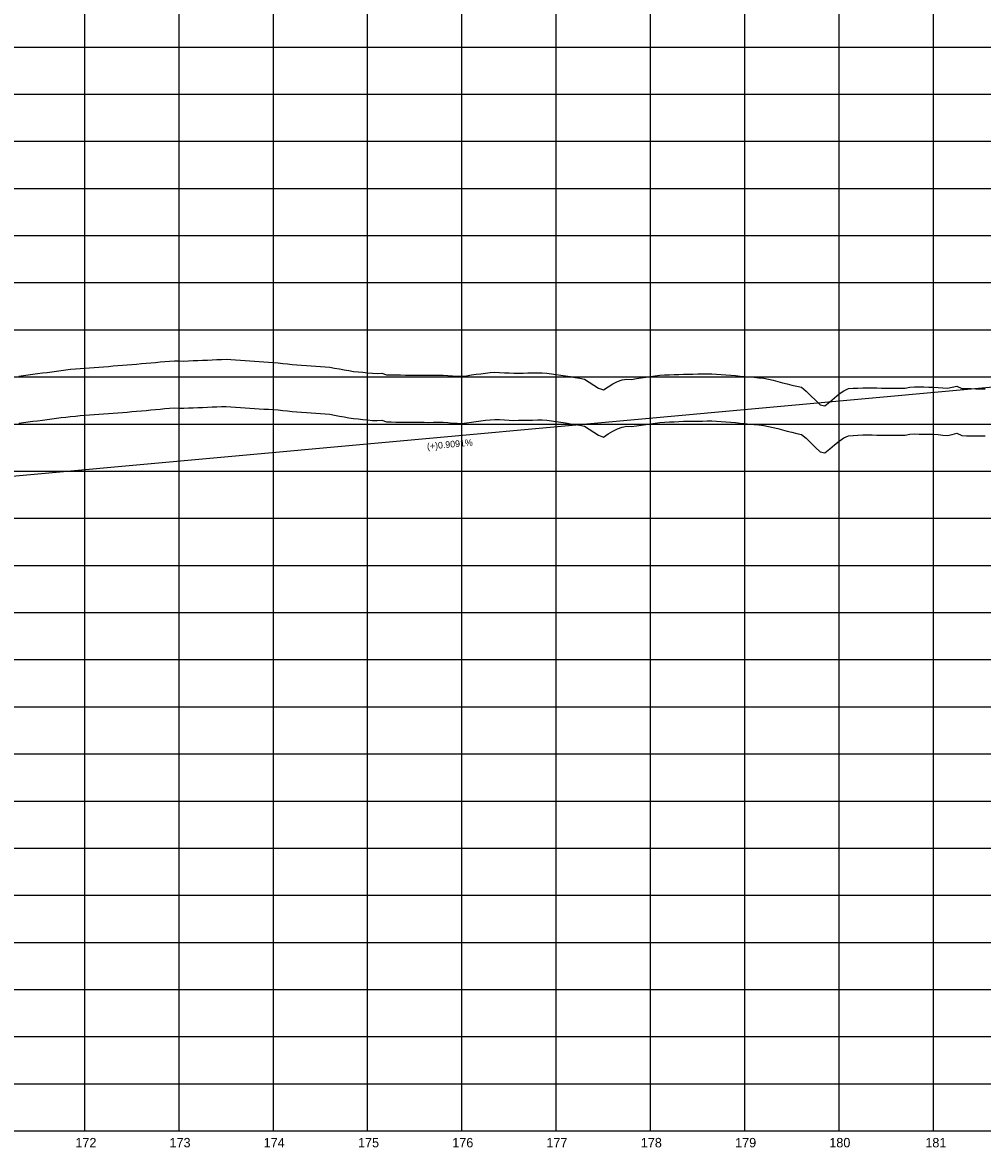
# Model space of a CAD drawing. Extents: x 2345490 to 2436403, y 465165 to 573888.
# Drawn here: x 2397455 to 2398474, y 564259 to 565453 of the extents above; entities that cross this region are included whole.
import ezdxf

# ---------------------------------------------------------------- set-up
doc = ezdxf.new("R2010")
doc.units = 0
for name, color, linetype in [('Old_Level_1', 7, 'Continuous'), ('Old_Level_2', 7, 'Continuous'), ('Old_Level_57', 7, 'Continuous'), ('Old_Level_62', 7, 'Continuous'), ('Old_Level_63', 7, 'Continuous')]:
    doc.layers.add(name, color=color, linetype=linetype)

msp = doc.modelspace()

# ---------------------------------------------------------------- linework, layer by layer
at = {"layer": 'Old_Level_1'}
for points in [[(2397451.5425, 565027.46875), (2397456.5425, 565028.1175), (2397461.5425, 565028.7665), (2397466.5425, 565029.41625), (2397471.5425, 565030.06625), (2397476.5425, 565030.7165), (2397481.5425, 565031.36725), (2397486.5425, 565032.0185), (2397491.5425, 565032.66975), (2397496.5425, 565033.3215), (2397501.5425, 565033.9735), (2397506.5425, 565034.6435), (2397511.5425, 565035.028), (2397516.5425, 565035.4135), (2397521.5425, 565035.7995), (2397526.5425, 565036.18575), (2397531.5425, 565036.572), (2397536.5425, 565036.9585), (2397541.5425, 565037.34475), (2397546.5425, 565037.73125), (2397551.5425, 565038.11775), (2397556.5425, 565038.504), (2397561.5425, 565038.87125), (2397566.5425, 565039.2175), (2397571.5425, 565039.67525), (2397576.5425, 565040.13325), (2397581.5425, 565040.59125), (2397586.5425, 565041.04925), (2397591.5425, 565041.507), (2397596.5425, 565041.965), (2397601.5425, 565042.423), (2397606.5425, 565042.881), (2397611.5425, 565043.33875), (2397616.5425, 565043.692), (2397621.5425, 565043.45175), (2397626.5425, 565043.3995), (2397631.5425, 565043.61025), (2397636.5425, 565043.82075), (2397641.5425, 565044.0315), (2397646.5425, 565044.24225), (2397651.5425, 565044.453), (2397656.5425, 565044.66375), (2397661.5425, 565044.87425), (2397666.5425, 565045.085), (2397671.5425, 565045.23025), (2397676.5425, 565044.883), (2397681.5425, 565044.53575), (2397686.5425, 565044.1885), (2397691.5425, 565043.8415), (2397696.5425, 565043.49425), (2397701.5425, 565043.147), (2397706.5425, 565042.79975), (2397711.5425, 565042.45825), (2397716.5425, 565042.1485), (2397721.5425, 565041.83875), (2397726.5425, 565041.50575), (2397731.5425, 565040.934), (2397736.5425, 565040.362), (2397741.5425, 565039.79025), (2397746.5425, 565039.33375), (2397751.5425, 565038.98775), (2397756.5425, 565038.64175), (2397761.5425, 565038.29575), (2397766.5425, 565037.94975), (2397771.5425, 565037.60375), (2397776.5425, 565037.25775), (2397781.5425, 565036.88175), (2397786.5425, 565035.95075), (2397791.5425, 565035.01975), (2397796.5425, 565034.08875), (2397801.5425, 565033.15775), (2397806.5425, 565032.35325), (2397811.5425, 565031.87325), (2397816.5425, 565031.3935), (2397821.5425, 565030.91375), (2397826.5425, 565030.434), (2397831.5425, 565030.1065), (2397836.5425, 565030.6725), (2397841.5425, 565028.777), (2397846.5425, 565028.70625), (2397851.5425, 565028.63575), (2397856.5425, 565028.565), (2397861.5425, 565028.51), (2397866.5425, 565028.47725), (2397871.5425, 565028.4445)], [(2397871.5425, 565028.4445), (2397876.5425, 565028.4115), (2397881.5425, 565028.37875), (2397886.5425, 565028.302), (2397891.5425, 565028.38125), (2397896.5425, 565028.538), (2397901.5425, 565028.5315), (2397906.5425, 565028.07125), (2397911.5425, 565027.611), (2397916.5425, 565027.3155), (2397921.5425, 565027.202), (2397926.5425, 565027.81325), (2397931.5425, 565028.598), (2397936.5425, 565029.364), (2397941.5425, 565029.94125), (2397946.5425, 565030.5185), (2397951.5425, 565031.09575), (2397956.5425, 565031.50725), (2397961.5425, 565031.24075), (2397966.5425, 565030.974), (2397971.5425, 565030.7075), (2397976.5425, 565030.44075), (2397981.5425, 565030.5155), (2397986.5425, 565030.64775), (2397991.5425, 565030.72575), (2397996.5425, 565030.80025), (2398001.5425, 565030.87475), (2398006.5425, 565030.88675), (2398011.5425, 565030.494), (2398016.5425, 565029.842), (2398021.5425, 565029.254), (2398026.5425, 565028.4445), (2398031.5425, 565027.635), (2398036.5425, 565026.82275), (2398041.5425, 565025.98475), (2398046.5425, 565025.176), (2398051.5425, 565024.1925), (2398056.5425, 565021.035), (2398061.5425, 565017.8775), (2398066.5425, 565014.72), (2398071.5425, 565012.761), (2398076.5425, 565016.1675), (2398081.5425, 565019.10675), (2398086.5425, 565021.56925), (2398091.5425, 565023.3685), (2398096.5425, 565024.22075), (2398101.5425, 565023.91375), (2398106.5425, 565024.713), (2398111.5425, 565025.427), (2398116.5425, 565026.14125), (2398121.5425, 565026.8555), (2398126.5425, 565027.56975), (2398131.5425, 565028.284), (2398136.5425, 565028.60275), (2398141.5425, 565028.78475), (2398146.5425, 565028.99425), (2398151.5425, 565029.20375), (2398156.5425, 565029.41325), (2398161.5425, 565029.48425), (2398166.5425, 565029.558), (2398171.5425, 565029.6315), (2398176.5425, 565029.705), (2398181.5425, 565029.7785), (2398186.5425, 565029.85225), (2398191.5425, 565029.5405), (2398196.5425, 565029.18525), (2398201.5425, 565028.83), (2398206.5425, 565028.47475), (2398211.5425, 565027.996), (2398216.5425, 565027.49325), (2398221.5425, 565027.016), (2398226.5425, 565026.554), (2398231.5425, 565026.08325), (2398236.5425, 565025.6125), (2398241.5425, 565025.05075), (2398246.5425, 565024.036), (2398251.5425, 565022.9735), (2398256.5425, 565021.66825), (2398261.5425, 565020.36275), (2398266.5425, 565019.1175), (2398271.5425, 565017.9365), (2398276.5425, 565016.6495), (2398281.5425, 565015.506), (2398286.5425, 565011.4535), (2398291.5425, 565006.60675), (2398296.5425, 565001.75975), (2398301.5425, 564996.91275), (2398306.5425, 564995.989), (2398311.5425, 565000.164), (2398316.5425, 565004.33925), (2398321.5425, 565008.5145), (2398326.5425, 565011.773), (2398331.5425, 565014.157), (2398336.5425, 565014.42525), (2398341.5425, 565014.6935), (2398346.5425, 565014.9615), (2398351.5425, 565015.107), (2398356.5425, 565014.97475), (2398361.5425, 565014.84275), (2398366.5425, 565014.7105), (2398371.5425, 565014.63575)], [(2398371.5425, 565014.63575), (2398376.5425, 565014.647), (2398381.5425, 565014.65825), (2398386.5425, 565014.6695), (2398391.5425, 565014.73525), (2398396.5425, 565015.76575), (2398401.5425, 565015.97825), (2398406.5425, 565015.9255), (2398411.5425, 565015.87275), (2398416.5425, 565015.82), (2398421.5425, 565015.74225), (2398426.5425, 565015.30925), (2398431.5425, 565014.87625), (2398436.5425, 565014.4875), (2398441.5425, 565015.56425), (2398446.5425, 565016.79025), (2398451.5425, 565014.18875), (2398456.5425, 565014.1245), (2398461.5425, 565014.06), (2398466.5425, 565013.9955), (2398471.5425, 565013.931), (2398476.5425, 565013.86675)]]:
    msp.add_lwpolyline(points, dxfattribs=at)
at = {"layer": 'Old_Level_2'}
msp.add_line((2396821.5425, 564914.71575), (2398621.5425, 565078.352), dxfattribs=at)
at = {"layer": 'Old_Level_57'}
for p, q in [((2397521.54225, 564276.534), (2397521.54225, 566615.2835)), ((2397621.54225, 564276.534), (2397621.54225, 566615.2835)), ((2397721.54225, 564276.534), (2397721.54225, 566615.2835)), ((2397821.54225, 564276.534), (2397821.54225, 566615.2835)), ((2397921.54225, 564276.534), (2397921.54225, 566615.2835)), ((2398021.54225, 564276.534), (2398021.54225, 566615.2835)), ((2398021.54225, 564276.534), (2398021.54225, 566615.2835)), ((2398121.54225, 564276.534), (2398121.54225, 566615.2835)), ((2398121.54225, 564276.534), (2398121.54225, 566615.2835)), ((2398221.54225, 564276.534), (2398221.54225, 566615.2835)), ((2398221.54225, 564276.534), (2398221.54225, 566615.2835)), ((2398321.5425, 564276.534), (2398321.5425, 566615.2835)), ((2398321.5425, 564276.534), (2398321.5425, 566615.2835)), ((2398421.54225, 564276.534), (2398421.54225, 566615.2835)), ((2381271.5425, 565426.534), (2410861.12275, 565426.534)), ((2381271.5425, 565376.534), (2410861.12275, 565376.534)), ((2381271.5425, 565326.534), (2410861.12275, 565326.534)), ((2381271.5425, 565276.534), (2410861.12275, 565276.534)), ((2381271.5425, 565226.534), (2410861.12275, 565226.534)), ((2381271.5425, 565176.534), (2410861.12275, 565176.534)), ((2381271.5425, 565126.534), (2410861.12275, 565126.534)), ((2381271.5425, 565076.534), (2410861.12275, 565076.534)), ((2381271.5425, 565026.534), (2410861.12275, 565026.534)), ((2381271.5425, 564976.534), (2410861.12275, 564976.534)), ((2381271.5425, 564926.534), (2410861.12275, 564926.534)), ((2381271.5425, 564876.534), (2410861.12275, 564876.534)), ((2381271.5425, 564826.534), (2410861.12275, 564826.534)), ((2381271.54275, 564776.534), (2410861.123, 564776.534)), ((2381271.5425, 564726.534), (2410861.12275, 564726.534)), ((2381271.54275, 564676.534), (2410861.123, 564676.534)), ((2381271.5425, 564626.534), (2410861.12275, 564626.534)), ((2381271.54275, 564576.534), (2410861.123, 564576.534)), ((2381271.5425, 564526.534), (2410861.12275, 564526.534)), ((2381271.54275, 564476.534), (2410861.123, 564476.534)), ((2381271.5425, 564426.534), (2410861.12275, 564426.534)), ((2381271.54275, 564376.534), (2410861.123, 564376.534)), ((2381271.5425, 564326.534), (2410861.12275, 564326.534)), ((2381271.54275, 564276.534), (2410861.123, 564276.534))]:
    msp.add_line(p, q, dxfattribs=at)
at = {"layer": 'Old_Level_63'}
msp.add_line((2381321.5425, 564276.534), (2406689.937, 564276.534), dxfattribs=at)
for points in [[(2397451.5425, 565077.4685), (2397456.5425, 565078.11725), (2397461.5425, 565078.76625), (2397466.5425, 565079.416), (2397471.5425, 565080.066), (2397476.5425, 565080.71625), (2397481.5425, 565081.367), (2397486.5425, 565082.01825), (2397491.5425, 565082.6695), (2397496.5425, 565083.32125), (2397501.5425, 565083.97325), (2397506.5425, 565084.64325), (2397511.5425, 565085.02775), (2397516.5425, 565085.41325), (2397521.5425, 565085.79925), (2397526.5425, 565086.1855), (2397531.5425, 565086.57175), (2397536.5425, 565086.95825), (2397541.5425, 565087.3445), (2397546.5425, 565087.731), (2397551.5425, 565088.1175), (2397556.5425, 565088.50375), (2397561.5425, 565088.871), (2397566.5425, 565089.21725), (2397571.5425, 565089.675), (2397576.5425, 565090.133), (2397581.5425, 565090.591), (2397586.5425, 565091.049), (2397591.5425, 565091.50675), (2397596.5425, 565091.96475), (2397601.5425, 565092.42275), (2397606.5425, 565092.88075), (2397611.5425, 565093.3385), (2397616.5425, 565093.69175), (2397621.5425, 565093.4515), (2397626.5425, 565093.39925), (2397631.5425, 565093.61), (2397636.5425, 565093.8205), (2397641.5425, 565094.03125), (2397646.5425, 565094.242), (2397651.5425, 565094.45275), (2397656.5425, 565094.6635), (2397661.5425, 565094.874), (2397666.5425, 565095.08475), (2397671.5425, 565095.23), (2397676.5425, 565094.88275), (2397681.5425, 565094.5355), (2397686.5425, 565094.18825), (2397691.5425, 565093.84125), (2397696.5425, 565093.494), (2397701.5425, 565093.14675), (2397706.5425, 565092.7995), (2397711.5425, 565092.458), (2397716.5425, 565092.14825), (2397721.5425, 565091.8385), (2397726.5425, 565091.5055), (2397731.5425, 565090.93375), (2397736.5425, 565090.36175), (2397741.5425, 565089.79), (2397746.5425, 565089.3335), (2397751.5425, 565088.9875), (2397756.5425, 565088.6415), (2397761.5425, 565088.2955), (2397766.5425, 565087.9495), (2397771.5425, 565087.6035), (2397776.5425, 565087.2575), (2397781.5425, 565086.8815), (2397786.5425, 565085.9505), (2397791.5425, 565085.0195), (2397796.5425, 565084.0885), (2397801.5425, 565083.1575), (2397806.5425, 565082.353), (2397811.5425, 565081.873), (2397816.5425, 565081.39325), (2397821.5425, 565080.9135), (2397826.5425, 565080.43375), (2397831.5425, 565080.10625), (2397836.5425, 565080.67225), (2397841.5425, 565078.77675), (2397846.5425, 565078.706), (2397851.5425, 565078.6355), (2397856.5425, 565078.56475), (2397861.5425, 565078.50975), (2397866.5425, 565078.477), (2397871.5425, 565078.44425)], [(2397871.5425, 565078.44425), (2397876.5425, 565078.41125), (2397881.5425, 565078.3785), (2397886.5425, 565078.30175), (2397891.5425, 565078.381), (2397896.5425, 565078.53775), (2397901.5425, 565078.53125), (2397906.5425, 565078.071), (2397911.5425, 565077.61075), (2397916.5425, 565077.31525), (2397921.5425, 565077.20175), (2397926.5425, 565077.813), (2397931.5425, 565078.59775), (2397936.5425, 565079.36375), (2397941.5425, 565079.941), (2397946.5425, 565080.51825), (2397951.5425, 565081.0955), (2397956.5425, 565081.507), (2397961.5425, 565081.2405), (2397966.5425, 565080.97375), (2397971.5425, 565080.70725), (2397976.5425, 565080.4405), (2397981.5425, 565080.51525), (2397986.5425, 565080.6475), (2397991.5425, 565080.7255), (2397996.5425, 565080.8), (2398001.5425, 565080.8745), (2398006.5425, 565080.8865), (2398011.5425, 565080.49375), (2398016.5425, 565079.84175), (2398021.5425, 565079.25375), (2398026.5425, 565078.44425), (2398031.5425, 565077.63475), (2398036.5425, 565076.8225), (2398041.5425, 565075.9845), (2398046.5425, 565075.17575), (2398051.5425, 565074.19225), (2398056.5425, 565071.03475), (2398061.5425, 565067.87725), (2398066.5425, 565064.71975), (2398071.5425, 565062.76075), (2398076.5425, 565066.16725), (2398081.5425, 565069.1065), (2398086.5425, 565071.569), (2398091.5425, 565073.36825), (2398096.5425, 565074.2205), (2398101.5425, 565073.9135), (2398106.5425, 565074.71275), (2398111.5425, 565075.42675), (2398116.5425, 565076.141), (2398121.5425, 565076.85525), (2398126.5425, 565077.5695), (2398131.5425, 565078.28375), (2398136.5425, 565078.6025), (2398141.5425, 565078.7845), (2398146.5425, 565078.994), (2398151.5425, 565079.2035), (2398156.5425, 565079.413), (2398161.5425, 565079.484), (2398166.5425, 565079.55775), (2398171.5425, 565079.63125), (2398176.5425, 565079.70475), (2398181.5425, 565079.77825), (2398186.5425, 565079.852), (2398191.5425, 565079.54025), (2398196.5425, 565079.185), (2398201.5425, 565078.82975), (2398206.5425, 565078.4745), (2398211.5425, 565077.99575), (2398216.5425, 565077.493), (2398221.5425, 565077.01575), (2398226.5425, 565076.55375), (2398231.5425, 565076.083), (2398236.5425, 565075.61225), (2398241.5425, 565075.0505), (2398246.5425, 565074.03575), (2398251.5425, 565072.97325), (2398256.5425, 565071.668), (2398261.5425, 565070.3625), (2398266.5425, 565069.11725), (2398271.5425, 565067.93625), (2398276.5425, 565066.64925), (2398281.5425, 565065.50575), (2398286.5425, 565061.45325), (2398291.5425, 565056.6065), (2398296.5425, 565051.7595), (2398301.5425, 565046.9125), (2398306.5425, 565045.98875), (2398311.5425, 565050.16375), (2398316.5425, 565054.339), (2398321.5425, 565058.51425), (2398326.5425, 565061.77275), (2398331.5425, 565064.15675), (2398336.5425, 565064.425), (2398341.5425, 565064.69325), (2398346.5425, 565064.96125), (2398351.5425, 565065.10675), (2398356.5425, 565064.9745), (2398361.5425, 565064.8425), (2398366.5425, 565064.71025), (2398371.5425, 565064.6355)], [(2398371.5425, 565064.6355), (2398376.5425, 565064.64675), (2398381.5425, 565064.658), (2398386.5425, 565064.66925), (2398391.5425, 565064.735), (2398396.5425, 565065.7655), (2398401.5425, 565065.978), (2398406.5425, 565065.92525), (2398411.5425, 565065.8725), (2398416.5425, 565065.81975), (2398421.5425, 565065.742), (2398426.5425, 565065.309), (2398431.5425, 565064.876), (2398436.5425, 565064.48725), (2398441.5425, 565065.564), (2398446.5425, 565066.79), (2398451.5425, 565064.1885), (2398456.5425, 565064.12425), (2398461.5425, 565064.05975), (2398466.5425, 565063.99525), (2398471.5425, 565063.93075), (2398476.5425, 565063.8665)]]:
    msp.add_lwpolyline(points, dxfattribs=at)

# ---------------------------------------------------------------- texts
at = {"layer": 'Old_Level_2'}
msp.add_text('(+)0.9091%', height=7.000001, rotation=5.19442778, dxfattribs=at).set_placement((2397884.76075, 564999.298))
at = {"layer": 'Old_Level_62'}
for s, p in [('172', (2397511.55925, 564259.034)), ('173', (2397611.394, 564259.034)), ('174', (2397711.2365, 564259.034)), ('175', (2397811.329, 564259.034)), ('176', (2397911.27, 564259.034)), ('177', (2398011.1275, 564259.034)), ('178', (2398111.25325, 564259.034)), ('179', (2398211.2955, 564259.034)), ('180', (2398311.1715, 564259.034)), ('181', (2398413.01075, 564259.034))]:
    msp.add_text(s, height=10.000001, dxfattribs=at).set_placement(p)

doc.saveas('drawing.dxf')
